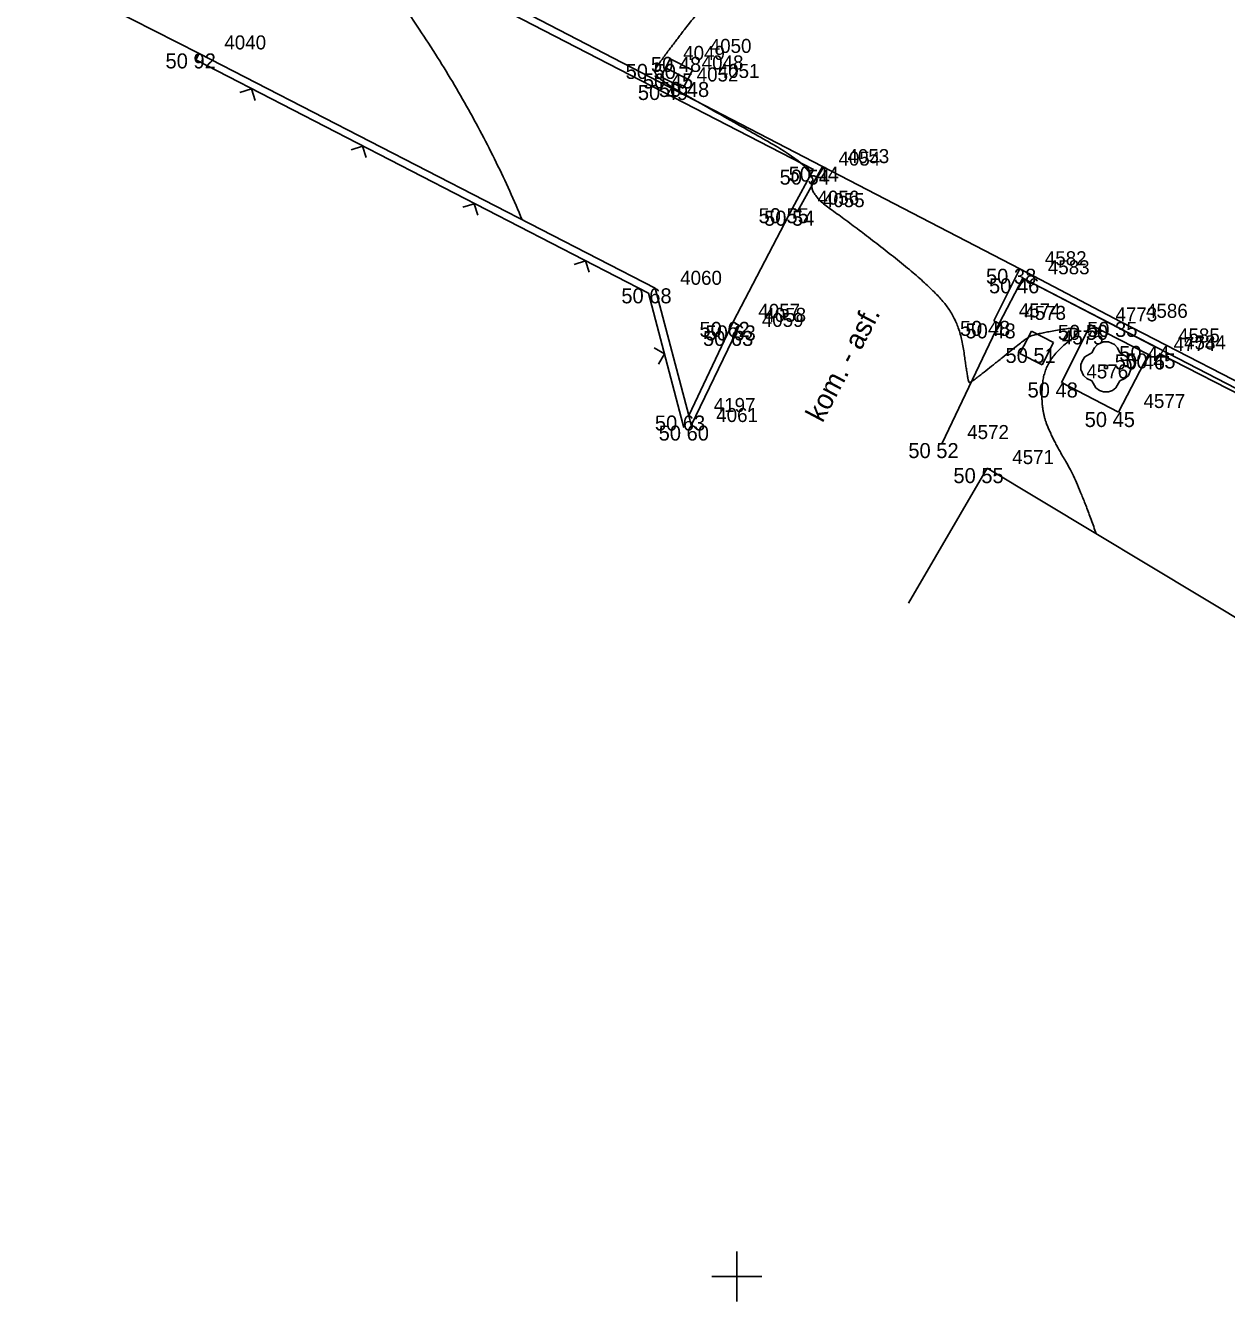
# Model space of a CAD drawing. Extents: x -704017 to -701500, y -1008977 to -1008450.
# Drawn here: x -701814.2 to -701790.22, y -1008950.5 to -1008925.02 of the extents above; entities that cross this region are included whole.
import ezdxf

# ---------------------------------------------------------------- set-up
doc = ezdxf.new("R2010")
doc.units = 0
for name, color, linetype in [('Z_body', 7, 'Continuous'), ('Z_body_cisla', 7, 'Continuous'), ('Z_body_vysky', 7, 'Continuous'), ('Z_budovy', 7, 'Continuous'), ('Z_hekt_sit', 7, 'Continuous'), ('Z_komunikace', 7, 'Continuous'), ('Z_obruby', 7, 'Continuous'), ('Z_oploceni', 7, 'Continuous'), ('Z_popis', 7, 'Continuous'), ('Z_rozhrani_ploch', 7, 'Continuous'), ('Z_site_znaky_kanalizace', 7, 'Continuous'), ('Z_site_znaky_nerozlisene', 7, 'Continuous'), ('Z_vrstevnice_vedlejsi', 7, 'Continuous'), ('Z_vstupy', 7, 'Continuous'), ('Z_zabradli', 7, 'Continuous'), ('Z_zelen_jednotliva', 7, 'Continuous')]:
    doc.layers.add(name, color=color, linetype=linetype)

# ---------------------------------------------------------------- blocks, each defined once
blk = doc.blocks.new('POINT_DISPLAY')
blk.add_line((0, 0), (0, 0))
blk = doc.blocks.new('Z212')
for p, q in [((-0.17, 0.17), (0, 0)), ((0, 0), (0.17, 0.17))]:
    blk.add_line(p, q)
blk = doc.blocks.new('Z38')
for p, q in [((0.25, 0.2), (-0.25, 0.2)), ((-0.25, 0.2), (-0.25, -0.2)), ((-0.25, 0), (0.25, 0)), ((0.25, -0.2), (0.25, 0.2)), ((-0.25, -0.2), (0.25, -0.2))]:
    blk.add_line(p, q)
blk = doc.blocks.new('Z608')
for p, q in [((0.25, 0.25), (-0.25, 0.25)), ((-0.25, 0.25), (-0.25, -0.25)), ((0.25, -0.25), (0.25, 0.25)), ((-0.25, -0.25), (0.25, -0.25))]:
    blk.add_line(p, q)
blk = doc.blocks.new('Z24')
for p, q in [((-0.42, 0.2), (-0.28, 0.28)), ((-0.28, 0.28), (-0.23, 0.38)), ((-0.23, 0.38), (-0.17, 0.45)), ((-0.17, 0.45), (-0.05, 0.5)), ((-0.05, 0.5), (0.05, 0.5)), ((0.05, 0.5), (0.17, 0.45)), ((0.17, 0.45), (0.23, 0.38)), ((0.23, 0.38), (0.28, 0.28)), ((0.28, 0.28), (0.42, 0.2)), ((-0.5, 0.05), (-0.47, 0.13)), ((-0.5, -0.05), (-0.5, 0.05)), ((-0.47, 0.13), (-0.42, 0.2)), ((-0.03, -0.03), (-0.03, 0.03)), ((-0.03, 0.03), (0.03, 0.03)), ((0.03, 0.03), (0.03, -0.03)), ((0.42, 0.2), (0.47, 0.13)), ((0.47, 0.13), (0.5, 0.05)), ((0.5, 0.05), (0.5, -0.05)), ((-0.45, -0.17), (-0.5, -0.05)), ((-0.38, -0.23), (-0.45, -0.17)), ((-0.28, -0.28), (-0.38, -0.23)), ((0.03, -0.03), (-0.03, -0.03)), ((0.38, -0.23), (0.28, -0.28)), ((0.45, -0.17), (0.38, -0.23)), ((0.5, -0.05), (0.45, -0.17)), ((-0.2, -0.42), (-0.28, -0.28)), ((-0.13, -0.47), (-0.2, -0.42)), ((-0.05, -0.5), (-0.13, -0.47)), ((0.05, -0.5), (-0.05, -0.5)), ((0.13, -0.47), (0.05, -0.5)), ((0.2, -0.42), (0.13, -0.47)), ((0.28, -0.28), (0.2, -0.42))]:
    blk.add_line(p, q)

msp = doc.modelspace()

# ---------------------------------------------------------------- linework, layer by layer
at = {"layer": 'Z_budovy'}
for p, q in [((-701795, -1008933.86), (-701796.57, -1008936.56)), ((-701786.73, -1008938.84), (-701795, -1008933.86))]:
    msp.add_line(p, q, dxfattribs=at)
at = {"layer": 'Z_hekt_sit'}
for p, q in [((-701800, -1008949.5), (-701800, -1008950.5)), ((-701800.5, -1008950), (-701799.5, -1008950))]:
    msp.add_line(p, q, dxfattribs=at)
at = {"layer": 'Z_komunikace'}
for p, q in [((-701807.55, -1008923.03), (-701798.29, -1008927.84)), ((-701798.29, -1008927.84), (-701798.78, -1008928.72)), ((-701798.89, -1008928.67), (-701800.07, -1008930.94)), ((-701798.78, -1008928.72), (-701798.89, -1008928.67)), ((-701794.87, -1008930.92), (-701794.35, -1008929.88)), ((-701794.35, -1008929.88), (-701792.33, -1008930.94)), ((-701800.07, -1008930.94), (-701799.95, -1008931.01)), ((-701799.95, -1008931.01), (-701800, -1008931.12)), ((-701795.9, -1008933.36), (-701794.76, -1008930.97)), ((-701794.76, -1008930.97), (-701794.87, -1008930.92)), ((-701792.33, -1008930.94), (-701777.69, -1008938.5))]:
    msp.add_line(p, q, dxfattribs=at)
at = {"layer": 'Z_obruby'}
for p, q in [((-701807.65, -1008923.15), (-701798.47, -1008927.9)), ((-701798.47, -1008927.9), (-701798.89, -1008928.67)), ((-701794.29, -1008930.07), (-701794.76, -1008930.97)), ((-701777.73, -1008938.63), (-701794.29, -1008930.07)), ((-701794.29, -1008930.07), (-701791.69, -1008931.42)), ((-701800.07, -1008930.94), (-701800.96, -1008932.81))]:
    msp.add_line(p, q, dxfattribs=at)
at = {"layer": 'Z_oploceni'}
for p, q in [((-701810.8, -1008925.71), (-701810.73, -1008925.58)), ((-701810.8, -1008925.71), (-701801.76, -1008930.37)), ((-701810.73, -1008925.58), (-701801.63, -1008930.27)), ((-701801.63, -1008930.27), (-701800.96, -1008932.81)), ((-701801.76, -1008930.37), (-701801.11, -1008932.85)), ((-701801.11, -1008932.85), (-701801.06, -1008933.05)), ((-701800.96, -1008932.81), (-701800.91, -1008933.01))]:
    msp.add_line(p, q, dxfattribs=at)
at = {"layer": 'Z_rozhrani_ploch'}
for p, q in [((-701794.35, -1008929.88), (-701798.29, -1008927.84)), ((-701792.94, -1008931), (-701793.52, -1008932.15)), ((-701791.78, -1008931.59), (-701792.94, -1008931)), ((-701800, -1008931.12), (-701800.91, -1008933.01)), ((-701792.38, -1008932.74), (-701791.78, -1008931.59)), ((-701793.52, -1008932.15), (-701792.38, -1008932.74))]:
    msp.add_line(p, q, dxfattribs=at)
at = {"layer": 'Z_vrstevnice_vedlejsi'}
for points in [[(-701804.284, -1008928.902), (-701805.114, -1008926.915), (-701807.65, -1008923.15), (-701808.369, -1008922.711), (-701810.075, -1008921.735), (-701809.115, -1008920.384), (-701806.708, -1008915.214), (-701806.77, -1008914.311), (-701805.685, -1008914.835), (-701803.231, -1008915.969), (-701802.817, -1008915.807), (-701802.443, -1008915.687), (-701801.81, -1008914.61), (-701801.75, -1008914.54), (-701801.95, -1008914.373)], [(-701792.824, -1008935.171), (-701793.2, -1008934.102), (-701793.69, -1008933.3), (-701793.943, -1008932.639), (-701793.847, -1008931.69), (-701792.94, -1008931), (-701794.066, -1008931.182), (-701794.26, -1008931.297), (-701795.33, -1008932.165), (-701795.385, -1008932.14), (-701795.547, -1008930.932), (-701796.173, -1008930.187), (-701797.672, -1008929.01), (-701798.584, -1008928.368), (-701798.398, -1008927.876), (-701800.936, -1008926.466), (-701801.691, -1008926.011), (-701801.57, -1008925.79), (-701800.432, -1008924.302), (-701799.28, -1008923.87), (-701799.227, -1008924.037), (-701798.384, -1008923.674), (-701798.088, -1008923.511), (-701797.958, -1008923.049), (-701798.205, -1008921.995), (-701798.57, -1008920.66), (-701798.548, -1008918.639), (-701798.785, -1008918.435), (-701798.178, -1008918.597), (-701797.256, -1008918.298), (-701797.334, -1008918.522), (-701797.557, -1008919.02), (-701795.375, -1008920.077), (-701794.425, -1008920.537), (-701794.515, -1008920.39), (-701792.696, -1008920.048), (-701792.027, -1008920.133), (-701791.388, -1008919.819), (-701792.7, -1008919.116)]]:
    msp.add_open_spline(points, degree=2, dxfattribs=at)
at = {"layer": 'Z_vstupy'}
msp.add_line((-701814.2, -1008923.82), (-701810.73, -1008925.58), dxfattribs=at)
at = {"layer": 'Z_zabradli'}
msp.add_line((-701777.73, -1008938.69), (-701791.57, -1008931.57), dxfattribs=at)

# ---------------------------------------------------------------- block references
at = {"layer": 'Z_body'}
for p in [(-701810.73, -1008925.58), (-701801.04, -1008925.65), (-701801.57, -1008925.79), (-701801.2, -1008925.98), (-701801.3, -1008926.21), (-701800.88, -1008926.15), (-701798.47, -1008927.9), (-701798.29, -1008927.84), (-701798.89, -1008928.67), (-701798.78, -1008928.72), (-701794.35, -1008929.88), (-701794.29, -1008930.07), (-701801.63, -1008930.27), (-701800.07, -1008930.94), (-701799.95, -1008931.01), (-701794.87, -1008930.92), (-701794.76, -1008930.97), (-701792.94, -1008931), (-701792.33, -1008930.94), (-701800, -1008931.12), (-701794.01, -1008931.46), (-701791.78, -1008931.59), (-701791.69, -1008931.42), (-701791.57, -1008931.57), (-701793.52, -1008932.15), (-701800.96, -1008932.81), (-701792.38, -1008932.74), (-701800.91, -1008933.01), (-701795.9, -1008933.36), (-701795, -1008933.86)]:
    msp.add_blockref('POINT_DISPLAY', p, dxfattribs=at)
at = {"layer": 'Z_oploceni'}
for p, rotation in [((-701809.69, -1008926.29), 152.7), ((-701807.47, -1008927.43), 152.7), ((-701805.24, -1008928.58), 152.7), ((-701803.02, -1008929.72), 152.7), ((-701801.44, -1008931.58), 104.8)]:
    msp.add_blockref('Z212', p, dxfattribs=dict(at, rotation=rotation))
at = {"layer": 'Z_site_znaky_kanalizace', "rotation": -27.000000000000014}
msp.add_blockref('Z38', (-701801.2, -1008925.98), dxfattribs=at)
at = {"layer": 'Z_site_znaky_nerozlisene', "rotation": -27.000000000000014}
msp.add_blockref('Z608', (-701794.01, -1008931.46), dxfattribs=at)
at = {"layer": 'Z_zelen_jednotliva'}
msp.add_blockref('Z24', (-701792.63, -1008931.84), dxfattribs=at)

# ---------------------------------------------------------------- texts
at = {"layer": 'Z_body_cisla'}
for s, p in [('4040', (-701810.23, -1008925.5)), ('4049', (-701801.07, -1008925.71)), ('4050', (-701800.54, -1008925.57)), ('4048', (-701800.7, -1008925.9)), ('4052', (-701800.8, -1008926.14)), ('4051', (-701800.38, -1008926.07)), ('4053', (-701797.79, -1008927.77)), ('4054', (-701797.97, -1008927.82)), ('4056', (-701798.39, -1008928.6)), ('4055', (-701798.28, -1008928.65)), ('4582', (-701793.85, -1008929.81)), ('4583', (-701793.79, -1008929.99)), ('4060', (-701801.13, -1008930.2)), ('4057', (-701799.57, -1008930.86)), ('4574', (-701794.37, -1008930.85)), ('4586', (-701791.83, -1008930.86)), ('4059', (-701799.5, -1008931.04)), ('4058', (-701799.45, -1008930.94)), ('4573', (-701794.26, -1008930.9)), ('4773', (-701792.44, -1008930.93)), ('4585', (-701791.19, -1008931.35)), ('4575', (-701793.51, -1008931.39)), ('4774', (-701791.28, -1008931.52)), ('4584', (-701791.07, -1008931.49)), ('4576', (-701793.02, -1008932.07)), ('4197', (-701800.46, -1008932.74)), ('4577', (-701791.88, -1008932.66)), ('4061', (-701800.41, -1008932.94)), ('4572', (-701795.4, -1008933.28)), ('4571', (-701794.5, -1008933.78))]:
    msp.add_text(s, height=0.28, dxfattribs=at).set_placement(p)
at = {"layer": 'Z_body_vysky'}
for s, p in [('50 92', (-701811.405, -1008925.88)), ('50 48', (-701801.715, -1008925.95)), ('50 50', (-701802.22, -1008926.09)), ('50 45', (-701801.875, -1008926.28)), ('50 49', (-701801.975, -1008926.51)), ('50 48', (-701801.555, -1008926.45)), ('50 54', (-701799.145, -1008928.2)), ('50 44', (-701798.965, -1008928.14)), ('50 55', (-701799.565, -1008928.97)), ('50 54', (-701799.455, -1008929.02)), ('50 38', (-701795.025, -1008930.18)), ('50 46', (-701794.965, -1008930.37)), ('50 68', (-701802.305, -1008930.57)), ('50 62', (-701800.745, -1008931.24)), ('50 63', (-701800.625, -1008931.31)), ('50 48', (-701795.545, -1008931.22)), ('50 48', (-701795.435, -1008931.27)), ('50 50', (-701793.59, -1008931.3)), ('50 35', (-701793.005, -1008931.24)), ('50 63', (-701800.675, -1008931.42)), ('50 51', (-701794.635, -1008931.76)), ('50 46', (-701792.455, -1008931.89)), ('50 44', (-701792.365, -1008931.72)), ('50 45', (-701792.245, -1008931.87)), ('50 48', (-701794.195, -1008932.45)), ('50 63', (-701801.635, -1008933.11)), ('50 45', (-701793.055, -1008933.04)), ('50 60', (-701801.56, -1008933.31)), ('50 52', (-701796.575, -1008933.66)), ('50 55', (-701795.675, -1008934.16))]:
    msp.add_text(s, height=0.3, dxfattribs=at).set_placement(p)
at = {"layer": 'Z_popis'}
msp.add_text('kom. - asf.', height=0.4, rotation=62.1, dxfattribs=at).set_placement((-701798.29, -1008932.97))

doc.saveas('drawing.dxf')
